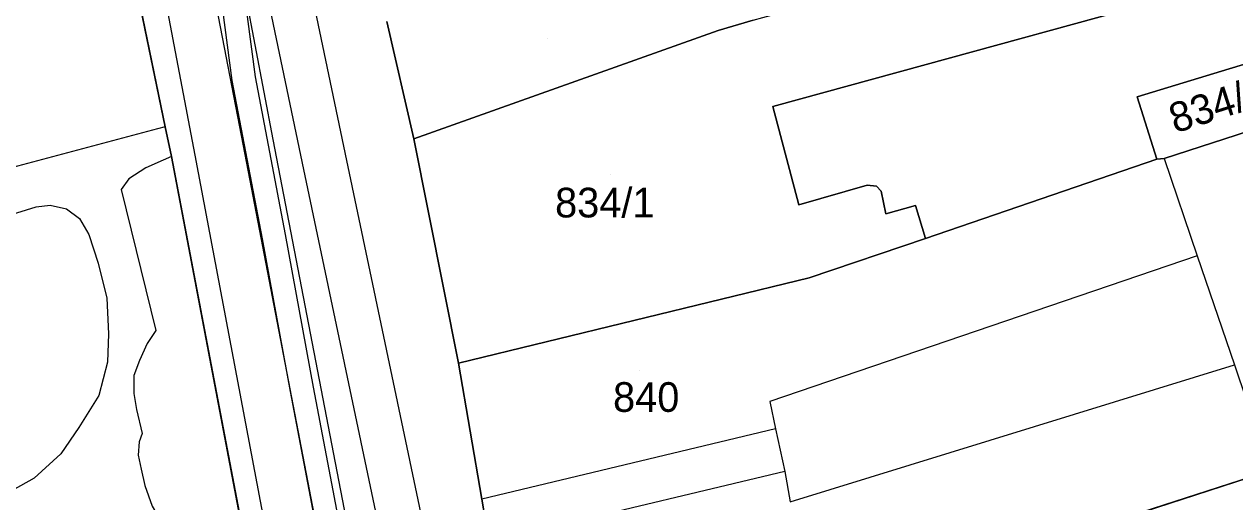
# Model space of a CAD drawing. Extents: x -263423 to -261326, y -1240067 to -1237864.
# Drawn here: x -262739.6 to -262658.2, y -1239703.5 to -1239671.3 of the extents above; entities that cross this region are included whole.
import ezdxf

# ---------------------------------------------------------------- set-up
doc = ezdxf.new("R2010")
doc.units = 0
for name, color, linetype in [('body_kn', 7, 'Continuous'), ('kladpar_druhypozemkov', 7, 'Continuous'), ('kladpar_hranice', 7, 'Continuous'), ('kladpar_parcelnecisla', 7, 'Continuous'), ('kladpar_plochy', 7, 'Continuous'), ('tarchy_linie', 7, 'Continuous'), ('zappar_hrandruhpozemk', 7, 'Continuous')]:
    doc.layers.add(name, color=color, linetype=linetype)

msp = doc.modelspace()

# ---------------------------------------------------------------- linework, layer by layer
at = {"layer": 'body_kn'}
for p, q in [((-262692.93, -1239671.72), (-262692.93, -1239671.72)), ((-262692.93, -1239671.72), (-262692.93, -1239671.72)), ((-262725.65, -1239675.1), (-262725.65, -1239675.1)), ((-262724.09, -1239674.85), (-262724.09, -1239674.85)), ((-262664.74, -1239676.19), (-262664.74, -1239676.19)), ((-262689.25, -1239676.84), (-262689.25, -1239676.84)), ((-262730.66, -1239678.36), (-262730.66, -1239678.36)), ((-262730.13, -1239678.22), (-262730.13, -1239678.22)), ((-262730.13, -1239678.22), (-262730.13, -1239678.22)), ((-262722.9, -1239679.06), (-262722.9, -1239679.06)), ((-262713.4, -1239679.02), (-262713.4, -1239679.02)), ((-262729.72, -1239680.22), (-262729.72, -1239680.22)), ((-262729.72, -1239680.22), (-262729.72, -1239680.22)), ((-262728.13, -1239680.12), (-262728.13, -1239680.12)), ((-262724.9, -1239679.49), (-262724.9, -1239679.49)), ((-262731.43, -1239680.97), (-262731.43, -1239680.97)), ((-262730.28, -1239680.47), (-262730.28, -1239680.47)), ((-262720.83, -1239681.08), (-262720.83, -1239681.08)), ((-262717.94, -1239680.48), (-262717.94, -1239680.48)), ((-262663.42, -1239680.4), (-262663.42, -1239680.4)), ((-262663.42, -1239680.4), (-262663.42, -1239680.4)), ((-262662.91, -1239680.34), (-262662.91, -1239680.34)), ((-262662.91, -1239680.34), (-262662.91, -1239680.34)), ((-262732.58, -1239681.73), (-262732.58, -1239681.73)), ((-262733.09, -1239682.43), (-262733.09, -1239682.43)), ((-262682.91, -1239682.15), (-262682.91, -1239682.15)), ((-262682.27, -1239682.22), (-262682.27, -1239682.22)), ((-262681.95, -1239682.54), (-262681.95, -1239682.54)), ((-262737.87, -1239683.49), (-262737.87, -1239683.49)), ((-262687.5, -1239683.47), (-262687.5, -1239683.47)), ((-262679.66, -1239683.51), (-262679.66, -1239683.51)), ((-262738.83, -1239683.61), (-262738.83, -1239683.61)), ((-262736.79, -1239683.75), (-262736.79, -1239683.75)), ((-262681.64, -1239684.07), (-262681.64, -1239684.07)), ((-262735.9, -1239684.39), (-262735.9, -1239684.39)), ((-262735.27, -1239685.47), (-262735.27, -1239685.47)), ((-262723.62, -1239685.77), (-262723.62, -1239685.77)), ((-262722.07, -1239685.48), (-262722.07, -1239685.48)), ((-262678.97, -1239685.74), (-262678.97, -1239685.74)), ((-262734.64, -1239687.39), (-262734.64, -1239687.39)), ((-262660.7, -1239686.91), (-262660.7, -1239686.91)), ((-262686.81, -1239688.38), (-262686.81, -1239688.38)), ((-262734.07, -1239689.75), (-262734.07, -1239689.75)), ((-262733.96, -1239692.17), (-262733.96, -1239692.17)), ((-262730.77, -1239691.93), (-262730.77, -1239691.93)), ((-262731.35, -1239692.82), (-262731.35, -1239692.82)), ((-262734.03, -1239694.08), (-262734.03, -1239694.08)), ((-262731.86, -1239693.96), (-262731.86, -1239693.96)), ((-262710.4, -1239694.13), (-262710.4, -1239694.13)), ((-262658.18, -1239694.24), (-262658.18, -1239694.24)), ((-262732.25, -1239694.98), (-262732.25, -1239694.98)), ((-262720.17, -1239695.75), (-262720.17, -1239695.75)), ((-262734.61, -1239696.31), (-262734.61, -1239696.31)), ((-262732.25, -1239696.19), (-262732.25, -1239696.19)), ((-262721.72, -1239696.04), (-262721.72, -1239696.04)), ((-262732.06, -1239697.27), (-262732.06, -1239697.27)), ((-262689.46, -1239696.71), (-262689.46, -1239696.71)), ((-262735.95, -1239698.47), (-262735.95, -1239698.47)), ((-262731.69, -1239698.87), (-262731.69, -1239698.87)), ((-262689.08, -1239698.56), (-262689.08, -1239698.56)), ((-262689.08, -1239698.56), (-262689.08, -1239698.56)), ((-262731.88, -1239699.44), (-262731.88, -1239699.44)), ((-262737.17, -1239700.24), (-262737.17, -1239700.24)), ((-262731.95, -1239700.33), (-262731.95, -1239700.33)), ((-262731.76, -1239701.29), (-262731.76, -1239701.29)), ((-262688.45, -1239701.43), (-262688.45, -1239701.43)), ((-262688.45, -1239701.43), (-262688.45, -1239701.43)), ((-262738.96, -1239701.89), (-262738.96, -1239701.89)), ((-262731.51, -1239702.37), (-262731.51, -1239702.37)), ((-262708.84, -1239703.31), (-262708.84, -1239703.31)), ((-262688.08, -1239703.47), (-262688.08, -1239703.47))]:
    msp.add_line(p, q, dxfattribs=at)
at = {"layer": 'kladpar_druhypozemkov'}
for p, q in [((-262704.38, -1239672.27), (-262704.38, -1239672.27)), ((-262658.74, -1239675.12), (-262658.74, -1239675.12)), ((-262700.14, -1239681.42), (-262700.14, -1239681.42)), ((-262698.24, -1239694.62), (-262698.24, -1239694.62))]:
    msp.add_line(p, q, dxfattribs=at)
at = {"layer": 'kladpar_hranice'}
for points in [[(-262740.91, -1239625.89), (-262730.13, -1239678.22), (-262729.72, -1239680.22), (-262721.69, -1239722.43), (-262721.35, -1239724.22), (-262718.29, -1239740.35), (-262718.21, -1239740.75), (-262722.08, -1239740.82), (-262725.23, -1239741.33), (-262730.64, -1239742.58), (-262733.98, -1239743.76), (-262738.34, -1239745.97), (-262739.76, -1239747.13)], [(-262739.76, -1239747.13), (-262738.34, -1239745.97), (-262733.98, -1239743.76), (-262730.64, -1239742.58), (-262725.23, -1239741.33), (-262722.08, -1239740.82), (-262718.21, -1239740.75), (-262718.29, -1239740.35), (-262721.35, -1239724.22), (-262721.69, -1239722.43), (-262729.72, -1239680.22), (-262730.13, -1239678.22), (-262740.91, -1239625.89)], [(-262692.93, -1239671.72), (-262690.57, -1239671.03), (-262689.93, -1239670.85), (-262682.6, -1239668.84), (-262677.57, -1239667.4), (-262676.87, -1239667.21), (-262655.45, -1239661.33), (-262653.88, -1239667.13), (-262689.25, -1239676.84), (-262687.5, -1239683.47), (-262682.91, -1239682.15), (-262682.27, -1239682.22), (-262681.95, -1239682.54), (-262681.64, -1239684.07), (-262679.66, -1239683.51), (-262678.97, -1239685.74), (-262686.81, -1239688.38), (-262710.4, -1239694.13), (-262713.4, -1239679.02), (-262692.93, -1239671.72)], [(-262632.63, -1239670.67), (-262650.8, -1239676.44), (-262651.55, -1239674.02), (-262652.12, -1239672.36), (-262664.74, -1239676.19), (-262663.42, -1239680.4), (-262678.97, -1239685.74), (-262679.66, -1239683.51), (-262681.64, -1239684.07), (-262681.95, -1239682.54), (-262682.27, -1239682.22), (-262682.91, -1239682.15), (-262687.5, -1239683.47), (-262689.25, -1239676.84), (-262653.88, -1239667.13)], [(-262690.57, -1239671.03), (-262692.93, -1239671.72), (-262713.4, -1239679.02), (-262715.22, -1239671.11)], [(-262715.22, -1239671.11), (-262713.4, -1239679.02), (-262710.4, -1239694.13), (-262708.84, -1239703.31), (-262708.34, -1239706.18), (-262706.78, -1239715.48), (-262705.97, -1239720.14), (-262705.72, -1239721.41), (-262704.92, -1239726.58), (-262703.11, -1239737.67), (-262701.62, -1239746.21), (-262700.06, -1239755.33), (-262700.51, -1239755.46), (-262699.32, -1239762.34), (-262698.58, -1239766.87), (-262697.57, -1239770.12)], [(-262652.12, -1239672.36), (-262651.55, -1239674.02), (-262650.8, -1239676.44), (-262653.98, -1239677.45), (-262662.91, -1239680.34), (-262663.42, -1239680.4), (-262664.74, -1239676.19), (-262652.12, -1239672.36)], [(-262663.42, -1239680.4), (-262662.91, -1239680.34), (-262653.98, -1239677.45), (-262652.28, -1239682.1), (-262648.37, -1239693.14), (-262646.55, -1239698.05), (-262650.82, -1239699.56), (-262655.79, -1239701.39), (-262656.36, -1239701.58), (-262679.06, -1239708.92), (-262706.78, -1239715.48), (-262708.34, -1239706.18), (-262708.84, -1239703.31), (-262710.4, -1239694.13), (-262686.81, -1239688.38), (-262678.97, -1239685.74), (-262663.42, -1239680.4)], [(-262679.06, -1239708.92), (-262656.36, -1239701.58), (-262655.48, -1239704.32), (-262654.35, -1239707.57), (-262648.8, -1239705.69), (-262649.94, -1239702.43), (-262650.82, -1239699.56), (-262646.55, -1239698.05), (-262635.46, -1239694.41), (-262638.53, -1239700.19), (-262638.47, -1239700.51), (-262638.41, -1239700.89), (-262638.47, -1239701.28), (-262638.86, -1239701.47), (-262639.44, -1239705.41), (-262661.25, -1239713.97), (-262661.25, -1239714.42), (-262683.05, -1239721.2), (-262682.93, -1239721.77), (-262704.92, -1239726.58), (-262705.72, -1239721.41), (-262705.97, -1239720.14), (-262706.78, -1239715.48)]]:
    msp.add_lwpolyline(points, dxfattribs=at)
at = {"layer": 'kladpar_plochy'}
for p, q in [((-262740.91, -1239625.89), (-262730.13, -1239678.22)), ((-262730.13, -1239678.22), (-262740.91, -1239625.89)), ((-262715.22, -1239671.11), (-262713.4, -1239679.02)), ((-262730.13, -1239678.22), (-262729.72, -1239680.22)), ((-262729.72, -1239680.22), (-262730.13, -1239678.22)), ((-262713.4, -1239679.02), (-262710.4, -1239694.13)), ((-262729.72, -1239680.22), (-262721.69, -1239722.43)), ((-262721.69, -1239722.43), (-262729.72, -1239680.22)), ((-262710.4, -1239694.13), (-262708.84, -1239703.31)), ((-262679.06, -1239708.92), (-262656.36, -1239701.58)), ((-262708.84, -1239703.31), (-262708.34, -1239706.18))]:
    msp.add_line(p, q, dxfattribs=at)
for points in [[(-262692.93, -1239671.72), (-262690.57, -1239671.03), (-262689.93, -1239670.85), (-262682.6, -1239668.84), (-262677.57, -1239667.4), (-262676.87, -1239667.21), (-262655.45, -1239661.33), (-262653.88, -1239667.13), (-262689.25, -1239676.84), (-262687.5, -1239683.47), (-262682.91, -1239682.15), (-262682.27, -1239682.22), (-262681.95, -1239682.54), (-262681.64, -1239684.07), (-262679.66, -1239683.51), (-262678.97, -1239685.74), (-262686.81, -1239688.38), (-262710.4, -1239694.13), (-262713.4, -1239679.02)], [(-262652.12, -1239672.36), (-262651.55, -1239674.02), (-262650.8, -1239676.44), (-262653.98, -1239677.45), (-262662.91, -1239680.34), (-262663.42, -1239680.4), (-262664.74, -1239676.19)], [(-262663.42, -1239680.4), (-262662.91, -1239680.34), (-262653.98, -1239677.45), (-262652.28, -1239682.1), (-262648.37, -1239693.14), (-262646.55, -1239698.05), (-262650.82, -1239699.56), (-262655.79, -1239701.39), (-262656.36, -1239701.58), (-262679.06, -1239708.92), (-262706.78, -1239715.48), (-262708.34, -1239706.18), (-262708.84, -1239703.31), (-262710.4, -1239694.13), (-262686.81, -1239688.38), (-262678.97, -1239685.74)]]:
    msp.add_lwpolyline(points, close=True, dxfattribs=at)
for points in [[(-262632.63, -1239670.67), (-262650.8, -1239676.44), (-262651.55, -1239674.02), (-262652.12, -1239672.36), (-262664.74, -1239676.19), (-262663.42, -1239680.4), (-262678.97, -1239685.74), (-262679.66, -1239683.51), (-262681.64, -1239684.07), (-262681.95, -1239682.54), (-262682.27, -1239682.22), (-262682.91, -1239682.15), (-262687.5, -1239683.47), (-262689.25, -1239676.84), (-262653.88, -1239667.13)], [(-262690.57, -1239671.03), (-262692.93, -1239671.72), (-262713.4, -1239679.02), (-262715.22, -1239671.11)]]:
    msp.add_lwpolyline(points, dxfattribs=at)
at = {"layer": 'tarchy_linie'}
for points in [[(-262876.1, -1239267.26), (-262859.65, -1239272.11), (-262836.46, -1239332.83), (-262813.8, -1239395.79), (-262782.96, -1239480.21), (-262751.68, -1239564.86), (-262738.56, -1239596.25), (-262720.83, -1239681.08), (-262703.16, -1239765.24), (-262676.39, -1239868.22), (-262673.88, -1239876.15)], [(-262748.93, -1239563.78), (-262735.73, -1239595.37), (-262717.94, -1239680.48), (-262700.29, -1239764.57), (-262673.55, -1239867.4)], [(-262739.93, -1239594.25), (-262736.99, -1239604.52), (-262734.56, -1239614.45), (-262732.52, -1239624.43), (-262730.56, -1239634.88), (-262728.68, -1239644.46), (-262726.88, -1239654.48), (-262725.41, -1239664.84), (-262724.09, -1239674.85), (-262722.07, -1239685.48), (-262720.17, -1239695.75), (-262718.35, -1239705.44), (-262716.4, -1239715.43), (-262714.36, -1239726.14), (-262712.35, -1239736.36), (-262709.13, -1239752.42), (-262707.17, -1239764.28), (-262706.65, -1239767.73), (-262706.19, -1239774), (-262705.77, -1239786.06), (-262699.88, -1239808.04), (-262689.6, -1239849.41)], [(-262741.39, -1239597.13), (-262726.59, -1239667.94), (-262725.65, -1239675.1), (-262723.62, -1239685.77), (-262721.72, -1239696.04), (-262719.9, -1239705.74), (-262717.95, -1239715.73), (-262715.91, -1239726.44), (-262713.89, -1239736.67), (-262710.68, -1239752.7), (-262708.73, -1239764.53), (-262708.22, -1239767.91), (-262707.76, -1239774.09), (-262707.34, -1239786.29), (-262701.41, -1239808.43), (-262691.04, -1239850.16)]]:
    msp.add_lwpolyline(points, dxfattribs=at)
at = {"layer": 'zappar_hrandruhpozemk'}
for p, q in [((-262731.81, -1239632.18), (-262722.9, -1239679.06)), ((-262733.86, -1239632.71), (-262724.9, -1239679.49)), ((-262728.13, -1239680.12), (-262736.98, -1239633.48)), ((-262730.66, -1239678.36), (-262744.49, -1239682.05)), ((-262730.13, -1239678.22), (-262730.66, -1239678.36)), ((-262662.91, -1239680.34), (-262660.7, -1239686.91)), ((-262757.51, -1239689.38), (-262738.83, -1239683.61)), ((-262660.7, -1239686.91), (-262689.46, -1239696.71)), ((-262689.08, -1239698.56), (-262708.84, -1239703.31)), ((-262731.76, -1239701.29), (-262731.51, -1239702.37)), ((-262688.45, -1239701.43), (-262708.34, -1239706.18))]:
    msp.add_line(p, q, dxfattribs=at)
for points in [[(-262722.9, -1239679.06), (-262711.38, -1239738.84), (-262709.03, -1239751.34)], [(-262729.72, -1239680.22), (-262730.28, -1239680.47), (-262731.43, -1239680.97), (-262732.58, -1239681.73), (-262733.09, -1239682.43), (-262730.77, -1239691.93), (-262731.35, -1239692.82), (-262731.86, -1239693.96), (-262732.25, -1239694.98), (-262732.25, -1239696.19), (-262732.06, -1239697.27), (-262731.69, -1239698.87), (-262731.88, -1239699.44), (-262731.95, -1239700.33), (-262731.76, -1239701.29)], [(-262714.44, -1239752.62), (-262716.75, -1239740.43), (-262728.13, -1239680.12)], [(-262724.9, -1239679.49), (-262713.41, -1239739.36), (-262711.07, -1239751.72), (-262709.96, -1239761.98), (-262709.78, -1239769.09)], [(-262738.83, -1239683.61), (-262737.87, -1239683.49), (-262736.79, -1239683.75), (-262735.9, -1239684.39), (-262735.27, -1239685.47), (-262734.64, -1239687.39), (-262734.07, -1239689.75), (-262733.96, -1239692.17), (-262734.03, -1239694.08), (-262734.61, -1239696.31), (-262735.95, -1239698.47), (-262737.17, -1239700.24), (-262738.96, -1239701.89), (-262741, -1239703.03)], [(-262660.7, -1239686.91), (-262658.18, -1239694.24), (-262655.79, -1239701.39)], [(-262689.46, -1239696.71), (-262689.08, -1239698.56), (-262688.45, -1239701.43), (-262688.08, -1239703.47), (-262658.18, -1239694.24)], [(-262731.51, -1239702.37), (-262731.01, -1239703.78), (-262730.12, -1239705.31), (-262729.17, -1239706.59), (-262725.53, -1239722.21), (-262725.22, -1239722.6), (-262724.71, -1239722.79), (-262722.1, -1239722.48), (-262721.69, -1239722.43)]]:
    msp.add_lwpolyline(points, dxfattribs=at)

# ---------------------------------------------------------------- texts
at = {"layer": 'kladpar_parcelnecisla'}
msp.add_text('834/2', height=2, rotation=18, dxfattribs=at).set_placement((-262662.182, -1239678.667))
for s, p in [('834/1', (-262703.903, -1239684.32)), ('840', (-262700.002, -1239697.42))]:
    msp.add_text(s, height=2, dxfattribs=at).set_placement(p)

doc.saveas('drawing.dxf')
